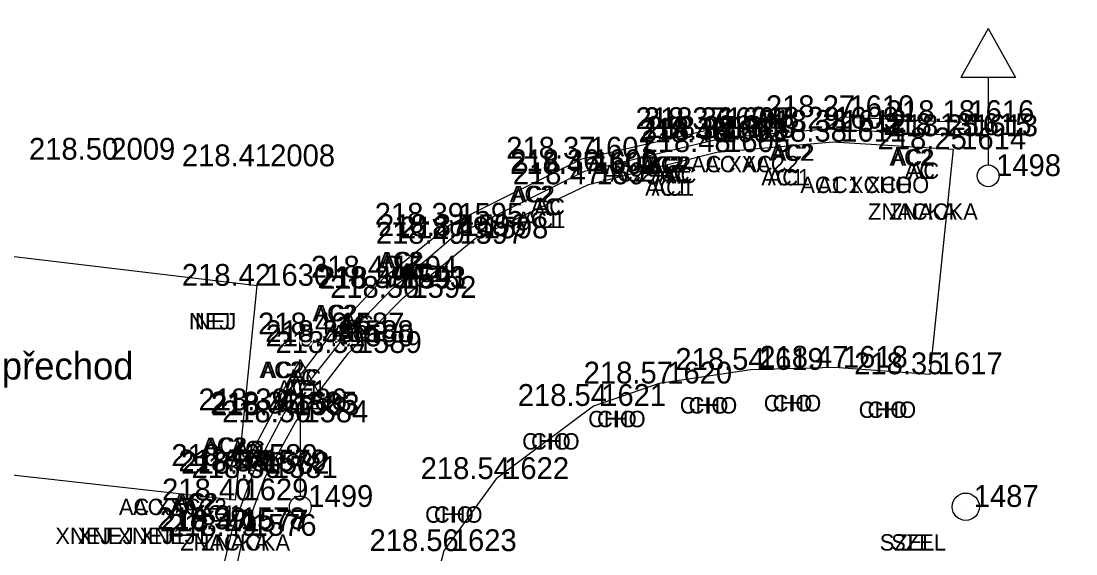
# Model space of a CAD drawing. Extents: x -471047 to -470889, y -1102859 to -1102000.
# Drawn here: x -470949.12 to -470929.78, y -1102399.08 to -1102389.32 of the extents above; entities that cross this region are included whole.
import ezdxf

# ---------------------------------------------------------------- set-up
doc = ezdxf.new("R2010")
doc.units = 0
for name, color, linetype in [('Vrstva 1', 7, 'Continuous'), ('Vrstva 19', 7, 'Continuous'), ('Vrstva 22', 7, 'Continuous'), ('Vrstva 23', 7, 'Continuous'), ('Vrstva 34', 7, 'Continuous'), ('Vrstva 35', 7, 'Continuous'), ('Vrstva 36', 7, 'Continuous'), ('Vrstva 38', 7, 'Continuous'), ('Vrstva 5', 7, 'Continuous'), ('Vrstva 7', 7, 'Continuous'), ('Vrstva 8', 7, 'Continuous'), ('Vrstva 9', 7, 'Continuous')]:
    doc.layers.add(name, color=color, linetype=linetype)

msp = doc.modelspace()

# ---------------------------------------------------------------- linework, layer by layer
at = {"layer": 'Vrstva 1'}
for points in [[(-471040.344, -1102858.385), (-471031.676, -1102846.187), (-471026.357, -1102838.629), (-471023.212, -1102833.975), (-471019.21, -1102827.465), (-471016.861, -1102823.272), (-471013.099, -1102815.912), (-471010.824, -1102810.955), (-471007.329, -1102802.292), (-471005.34, -1102796.515), (-471002.842, -1102787.838), (-471001.3, -1102780.997), (-471000.19, -1102774.713), (-470999.247, -1102768.204), (-470998.794, -1102764.784), (-470997.199, -1102751.812), (-470994.899, -1102732.807), (-470992.551, -1102713.262), (-470990.326, -1102694.887), (-470988.122, -1102676.57), (-470985.812, -1102657.305), (-470983.537, -1102638.407), (-470981.386, -1102620.622), (-470979.843, -1102608.014), (-470976.377, -1102579.253), (-470972.945, -1102550.69), (-470970.475, -1102530.206), (-470967.905, -1102508.801), (-470965.053, -1102485.131), (-470962.734, -1102465.9), (-470960.173, -1102444.812), (-470957.795, -1102425.103), (-470954.965, -1102401.839), (-470953.834, -1102392.574), (-470952.33, -1102379.985), (-470950.744, -1102366.853), (-470948.978, -1102352.106), (-470947.037, -1102335.844), (-470944.949, -1102318.462), (-470944.013, -1102310.745), (-470942.39, -1102297.267), (-470939.519, -1102273.45), (-470937.593, -1102257.43), (-470936.064, -1102244.81), (-470934.114, -1102228.634), (-470931.621, -1102207.856), (-470929.536, -1102190.857), (-470926.572, -1102166.31), (-470924.91, -1102152.663), (-470923.413, -1102140.333), (-470921.923, -1102127.669), (-470921.155, -1102120.084), (-470920.446, -1102109.574), (-470919.912, -1102099.137), (-470919.63, -1102088.981), (-470919.523, -1102081.193), (-470919.563, -1102070.395), (-470919.714, -1102064.236), (-470920.134, -1102054.704), (-470920.462, -1102047.615), (-470920.599, -1102044.52), (-470920.743, -1102041.873), (-470921.125, -1102034.455), (-470921.774, -1102030.337), (-470922.418, -1102027.787), (-470923.734, -1102023.93), (-470924.872, -1102021.434), (-470926.752, -1102018.182), (-470927.953, -1102016.45), (-470929.616, -1102014.424), (-470932.252, -1102011.756), (-470935.111, -1102009.425), (-470938.391, -1102007.371), (-470942.651, -1102005.401)], [(-471041.328, -1102857.18), (-471032.144, -1102844.242), (-471027.583, -1102837.763), (-471024.388, -1102833.028), (-471020.451, -1102826.6), (-471018.089, -1102822.378), (-471014.542, -1102815.445), (-471012.233, -1102810.418), (-471009.247, -1102803.108), (-471006.795, -1102796.098), (-471004.315, -1102787.532), (-471002.782, -1102780.723), (-471001.674, -1102774.458), (-471000.75, -1102768.095), (-471000.28, -1102764.601), (-470998.692, -1102751.741), (-470996.378, -1102732.635), (-470994.028, -1102713.058), (-470991.808, -1102694.749), (-470989.616, -1102676.447), (-470987.284, -1102657.013), (-470985.031, -1102638.272), (-470982.87, -1102620.431), (-470981.334, -1102607.933), (-470977.881, -1102579.263), (-470974.429, -1102550.492), (-470971.964, -1102530.054), (-470969.391, -1102508.607), (-470966.54, -1102484.984), (-470964.231, -1102465.853), (-470961.679, -1102444.752), (-470959.304, -1102425.078), (-470956.455, -1102401.634), (-470955.339, -1102392.489), (-470953.812, -1102379.71), (-470952.249, -1102366.808), (-470950.479, -1102352.023), (-470948.536, -1102335.868), (-470946.426, -1102318.233), (-470945.493, -1102310.531), (-470943.864, -1102297.013), (-470940.984, -1102273.071), (-470939.078, -1102257.195), (-470937.559, -1102244.684), (-470935.592, -1102228.353), (-470933.101, -1102207.653), (-470931.011, -1102190.57), (-470928.046, -1102166.021), (-470926.409, -1102152.578), (-470924.898, -1102140.121), (-470923.427, -1102127.544), (-470922.647, -1102119.826), (-470921.919, -1102109.229), (-470921.42, -1102099.134), (-470921.127, -1102089.016), (-470921.023, -1102081.453), (-470921.061, -1102070.468), (-470921.209, -1102064.314), (-470921.666, -1102053.966), (-470922.156, -1102043.345), (-470922.299, -1102039.934), (-470922.637, -1102034.36), (-470923.091, -1102031.241), (-470923.847, -1102028.247), (-470925.083, -1102024.594), (-470926.222, -1102022.086), (-470928.04, -1102018.943), (-470929.138, -1102017.357), (-470930.929, -1102015.175), (-470933.062, -1102013.049), (-470936.379, -1102010.368), (-470939.169, -1102008.662), (-470942.899, -1102006.906), (-470945.661, -1102005.908)], [(-471043.557, -1102855.955), (-471035.129, -1102844.026), (-471029.872, -1102836.499), (-471026.577, -1102831.578), (-471022.675, -1102825.415), (-471020.123, -1102821.053), (-471016.667, -1102814.59), (-471014.208, -1102809.45), (-471011.177, -1102802.451), (-471008.55, -1102795.333), (-471006.082, -1102787.209), (-471004.464, -1102780.376), (-471003.265, -1102774.167), (-471002.327, -1102767.948), (-471001.636, -1102762.527), (-471000.297, -1102751.605), (-470997.959, -1102732.524), (-470995.602, -1102712.802), (-470993.412, -1102694.623), (-470991.21, -1102676.17), (-470988.891, -1102656.857), (-470986.625, -1102638.083), (-470984.455, -1102620.195), (-470982.936, -1102607.733), (-470979.497, -1102579.223), (-470976.023, -1102550.279), (-470973.554, -1102529.822), (-470970.991, -1102508.497), (-470968.146, -1102484.787), (-470965.835, -1102465.72), (-470963.284, -1102444.529), (-470960.91, -1102424.942), (-470958.043, -1102401.343), (-470956.946, -1102392.356), (-470955.396, -1102379.408), (-470953.851, -1102366.636), (-470952.049, -1102351.733), (-470950.124, -1102335.611), (-470948.034, -1102318.083), (-470947.094, -1102310.328), (-470945.421, -1102296.51), (-470942.58, -1102272.848), (-470940.675, -1102256.948), (-470939.176, -1102244.526), (-470937.187, -1102228.174), (-470934.708, -1102207.467), (-470932.621, -1102190.433), (-470929.634, -1102165.778), (-470928.004, -1102152.415), (-470926.45, -1102139.595), (-470925.003, -1102127.418), (-470924.249, -1102119.695), (-470923.515, -1102109.093), (-470923.018, -1102099.069), (-470922.711, -1102088.911), (-470922.643, -1102081.356), (-470922.797, -1102070.414), (-470923.018, -1102064.454), (-470923.52, -1102053.203), (-470923.823, -1102047.529), (-470924.123, -1102041.506), (-470924.462, -1102037.486), (-470924.934, -1102031.904), (-470925.664, -1102028.672), (-470926.771, -1102025.506), (-470927.959, -1102022.914), (-470929.674, -1102020.028), (-470930.76, -1102018.498), (-470932.447, -1102016.478), (-470935.215, -1102013.816), (-470937.644, -1102011.98), (-470940.381, -1102010.371), (-470943.968, -1102008.669), (-470947.145, -1102007.524), (-470950.874, -1102006.74)], [(-471044.756, -1102855.056), (-471036.376, -1102843.177), (-471031.167, -1102835.741), (-471027.859, -1102830.8), (-471023.934, -1102824.593), (-471021.43, -1102820.312), (-471018.011, -1102813.91), (-471015.536, -1102808.75), (-471012.578, -1102801.897), (-471009.95, -1102794.77), (-471007.561, -1102786.914), (-471005.936, -1102780.074), (-471004.727, -1102773.818), (-471003.828, -1102767.827), (-471003.121, -1102762.345), (-471001.787, -1102751.467), (-470999.446, -1102732.348), (-470997.073, -1102712.539), (-470994.902, -1102694.521), (-470992.696, -1102676.023), (-470990.376, -1102656.68), (-470988.131, -1102638.071), (-470985.947, -1102620.018), (-470984.417, -1102607.512), (-470980.993, -1102579.08), (-470977.514, -1102550.137), (-470975.048, -1102529.649), (-470972.488, -1102508.37), (-470969.618, -1102484.508), (-470967.34, -1102465.669), (-470964.767, -1102444.39), (-470962.402, -1102424.781), (-470959.534, -1102401.193), (-470958.432, -1102392.151), (-470956.883, -1102379.208), (-470955.335, -1102366.424), (-470953.535, -1102351.506), (-470951.606, -1102335.399), (-470949.519, -1102317.94), (-470948.575, -1102310.159), (-470946.889, -1102296.144), (-470944.056, -1102272.618), (-470942.139, -1102256.659), (-470940.657, -1102244.341), (-470938.638, -1102227.749), (-470936.19, -1102207.298), (-470934.102, -1102190.255), (-470931.124, -1102165.639), (-470929.492, -1102152.254), (-470927.915, -1102139.252), (-470926.46, -1102127.103), (-470925.74, -1102119.604), (-470925.012, -1102108.913), (-470924.523, -1102099.054), (-470924.217, -1102088.866), (-470924.148, -1102081.334), (-470924.301, -1102070.391), (-470924.518, -1102064.43), (-470924.97, -1102054.435), (-470925.588, -1102041.569), (-470925.963, -1102035.313), (-470926.405, -1102032.225), (-470927.078, -1102029.198), (-470928.123, -1102026.148), (-470929.318, -1102023.558), (-470930.84, -1102020.97), (-470931.868, -1102019.515), (-470933.443, -1102017.605), (-470936.26, -1102014.885), (-470938.429, -1102013.255), (-470941.213, -1102011.639), (-470944.847, -1102009.927), (-470947.723, -1102008.912), (-470951.444, -1102008.161), (-470954.511, -1102007.931), (-470957.895, -1102008.041)]]:
    msp.add_spline(points, degree=3, dxfattribs=at)
at = {"layer": 'Vrstva 19'}
for p, q in [((-470931.386, -1102389.455), (-470931.886, -1102390.355)), ((-470931.386, -1102389.455), (-470930.886, -1102390.355)), ((-470930.886, -1102390.355), (-470931.886, -1102390.355)), ((-470931.386, -1102390.355), (-470931.386, -1102391.955)), ((-470943.999, -1102395.522), (-470944.499, -1102396.422)), ((-470943.999, -1102395.522), (-470943.499, -1102396.422)), ((-470943.499, -1102396.422), (-470944.499, -1102396.422)), ((-470943.999, -1102396.422), (-470943.999, -1102398.022))]:
    msp.add_line(p, q, dxfattribs=at)
for centre in [(-470931.386, -1102392.155), (-470943.999, -1102398.222)]:
    msp.add_circle(centre, 0.2, dxfattribs=at)
at = {"layer": 'Vrstva 23'}
msp.add_circle((-470931.799, -1102398.216), 0.25, dxfattribs=at)
at = {"layer": 'Vrstva 34'}
for p, q in [((-470934.08, -1102391.08), (-470934.08, -1102391.08)), ((-470936.47, -1102391.3), (-470936.47, -1102391.3)), ((-470936.34, -1102391.3), (-470936.34, -1102391.3)), ((-470934.36, -1102391.29), (-470934.36, -1102391.29)), ((-470931.88, -1102391.17), (-470931.88, -1102391.17)), ((-470936.44, -1102391.54), (-470936.44, -1102391.54)), ((-470936.38, -1102391.49), (-470936.38, -1102391.49)), ((-470936.27, -1102391.46), (-470936.27, -1102391.46)), ((-470934.23, -1102391.53), (-470934.23, -1102391.53)), ((-470934.22, -1102391.35), (-470934.22, -1102391.35)), ((-470931.93, -1102391.41), (-470931.93, -1102391.41)), ((-470931.81, -1102391.43), (-470931.81, -1102391.43)), ((-470936.36, -1102391.72), (-470936.36, -1102391.72)), ((-470932.03, -1102391.67), (-470932.03, -1102391.67)), ((-470947.63, -1102391.86), (-470947.63, -1102391.86)), ((-470938.84, -1102391.84), (-470938.84, -1102391.84)), ((-470944.7, -1102391.98), (-470944.7, -1102391.98)), ((-470938.79, -1102392.07), (-470938.79, -1102392.07)), ((-470938.77, -1102392.12), (-470938.77, -1102392.12)), ((-470938.72, -1102392.31), (-470938.72, -1102392.31)), ((-470931.39, -1102392.16), (-470931.39, -1102392.16)), ((-470941.25, -1102393.05), (-470941.25, -1102393.05)), ((-470941.19, -1102393.26), (-470941.19, -1102393.26)), ((-470941.23, -1102393.4), (-470941.23, -1102393.4)), ((-470940.79, -1102393.3), (-470940.79, -1102393.3)), ((-470942.46, -1102394.02), (-470942.46, -1102394.02)), ((-470944.79, -1102394.17), (-470944.79, -1102394.17)), ((-470942.3, -1102394.21), (-470942.3, -1102394.21)), ((-470942.27, -1102394.22), (-470942.27, -1102394.22)), ((-470942.11, -1102394.39), (-470942.11, -1102394.39)), ((-470943.43, -1102395.06), (-470943.43, -1102395.06)), ((-470943.26, -1102395.2), (-470943.26, -1102395.2)), ((-470943.25, -1102395.28), (-470943.25, -1102395.28)), ((-470943.11, -1102395.4), (-470943.11, -1102395.4)), ((-470935.74, -1102395.71), (-470935.74, -1102395.71)), ((-470934.2, -1102395.67), (-470934.2, -1102395.67)), ((-470932.46, -1102395.79), (-470932.46, -1102395.79)), ((-470937.42, -1102395.96), (-470937.42, -1102395.96)), ((-470938.63, -1102396.37), (-470938.63, -1102396.37)), ((-470944.48, -1102396.45), (-470944.48, -1102396.45)), ((-470944.29, -1102396.51), (-470944.29, -1102396.51)), ((-470944.25, -1102396.54), (-470944.25, -1102396.54)), ((-470944.09, -1102396.67), (-470944.09, -1102396.67)), ((-470945.02, -1102397.47), (-470945.02, -1102397.47)), ((-470944.85, -1102397.57), (-470944.85, -1102397.57)), ((-470944.8, -1102397.61), (-470944.8, -1102397.61)), ((-470944.65, -1102397.69), (-470944.65, -1102397.69)), ((-470940.41, -1102397.71), (-470940.41, -1102397.71)), ((-470945.19, -1102398.1), (-470945.19, -1102398.1)), ((-470944, -1102398.22), (-470944, -1102398.22)), ((-470931.8, -1102398.22), (-470931.8, -1102398.22)), ((-470945.24, -1102398.63), (-470945.24, -1102398.63)), ((-470945.19, -1102398.67), (-470945.19, -1102398.67)), ((-470945.04, -1102398.75), (-470945.04, -1102398.75)), ((-470941.37, -1102399.03), (-470941.37, -1102399.03))]:
    msp.add_line(p, q, dxfattribs=at)
at = {"layer": 'Vrstva 5'}
for p, q in [((-470934.361, -1102391.295), (-470934.079, -1102391.077)), ((-470934.079, -1102391.077), (-470931.877, -1102391.169)), ((-470938.837, -1102391.841), (-470936.466, -1102391.302)), ((-470936.466, -1102391.302), (-470936.341, -1102391.301)), ((-470936.341, -1102391.301), (-470936.273, -1102391.456)), ((-470941.249, -1102393.046), (-470938.837, -1102391.841)), ((-470942.463, -1102394.02), (-470941.249, -1102393.046)), ((-470943.432, -1102395.063), (-470942.463, -1102394.02)), ((-470944.48, -1102396.449), (-470943.432, -1102395.063)), ((-470945.023, -1102397.472), (-470944.48, -1102396.449)), ((-470944.852, -1102397.574), (-470945.023, -1102397.472))]:
    msp.add_line(p, q, dxfattribs=at)
at = {"layer": 'Vrstva 7'}
for p, q in [((-470936.361, -1102391.724), (-470934.235, -1102391.53)), ((-470934.235, -1102391.53), (-470932.026, -1102391.669)), ((-470938.716, -1102392.311), (-470936.361, -1102391.724)), ((-470940.791, -1102393.304), (-470938.716, -1102392.311)), ((-470942.113, -1102394.387), (-470940.791, -1102393.304)), ((-470943.113, -1102395.401), (-470942.113, -1102394.387)), ((-470944.086, -1102396.669), (-470943.113, -1102395.401)), ((-470944.652, -1102397.687), (-470944.086, -1102396.669)), ((-470945.038, -1102398.748), (-470944.652, -1102397.687)), ((-470945.474, -1102400.707), (-470945.038, -1102398.748))]:
    msp.add_line(p, q, dxfattribs=at)
at = {"layer": 'Vrstva 8'}
for p, q in [((-470936.273, -1102391.456), (-470934.361, -1102391.295)), ((-470934.361, -1102391.295), (-470931.928, -1102391.413)), ((-470938.791, -1102392.07), (-470936.381, -1102391.488)), ((-470936.381, -1102391.488), (-470936.273, -1102391.456)), ((-470932.026, -1102391.669), (-470932.459, -1102395.794)), ((-470941.189, -1102393.264), (-470938.791, -1102392.07)), ((-470942.304, -1102394.21), (-470941.189, -1102393.264)), ((-470943.264, -1102395.2), (-470942.304, -1102394.21)), ((-470944.295, -1102396.511), (-470943.264, -1102395.2)), ((-470935.737, -1102395.711), (-470937.417, -1102395.962)), ((-470934.203, -1102395.666), (-470935.737, -1102395.711)), ((-470932.459, -1102395.794), (-470934.203, -1102395.666)), ((-470937.417, -1102395.962), (-470938.626, -1102396.373)), ((-470938.626, -1102396.373), (-470940.408, -1102397.705)), ((-470944.852, -1102397.574), (-470944.295, -1102396.511)), ((-470945.241, -1102398.626), (-470944.852, -1102397.574)), ((-470940.408, -1102397.705), (-470941.368, -1102399.026)), ((-470945.724, -1102400.649), (-470945.241, -1102398.626)), ((-470941.368, -1102399.026), (-470942.101, -1102401.878))]:
    msp.add_line(p, q, dxfattribs=at)
at = {"layer": 'Vrstva 9'}
for p, q in [((-470944.791, -1102394.172), (-470950.548, -1102393.482)), ((-470945.189, -1102398.097), (-470944.791, -1102394.172)), ((-470945.189, -1102398.097), (-470951.095, -1102397.436))]:
    msp.add_line(p, q, dxfattribs=at)

# ---------------------------------------------------------------- texts
at = {"layer": 'Vrstva 22'}
msp.add_text('přechod', height=0.5, dxfattribs=at).set_placement((-470949.472, -1102395.886))
at = {"layer": 'Vrstva 35'}
for s, p in [('AC2', (-470935.396, -1102391.88)), ('AC2', (-470935.355, -1102391.88)), ('AC2', (-470933.196, -1102391.97)), ('AC2', (-470933.155, -1102391.97)), ('AC2', (-470937.786, -1102392.1)), ('AC2', (-470937.745, -1102392.1)), ('AC2', (-470937.656, -1102392.1)), ('AC2', (-470937.615, -1102392.1)), ('AC XAC2', (-470936.835, -1102392.09)), ('AC XAC2', (-470936.576, -1102392.09)), ('AC', (-470932.919, -1102392.21)), ('AC', (-470932.844, -1102392.21)), ('AC2 AC', (-470938.459, -1102392.26)), ('AC2 AC', (-470938.309, -1102392.26)), ('AC', (-470937.369, -1102392.29)), ('AC', (-470937.294, -1102392.29)), ('AC1', (-470935.547, -1102392.33)), ('AC1', (-470935.43, -1102392.33)), ('AC1', (-470937.677, -1102392.52)), ('AC1', (-470937.56, -1102392.52)), ('AC1 XCHO', (-470934.831, -1102392.47)), ('AC1 XCHO', (-470934.519, -1102392.47)), ('AC2', (-470940.156, -1102392.64)), ('AC2', (-470940.115, -1102392.64)), ('AC', (-470939.779, -1102392.87)), ('AC', (-470939.704, -1102392.87)), ('ZNACKA', (-470933.59, -1102392.96)), ('ZNACKA', (-470933.204, -1102392.96)), ('AC1', (-470940.037, -1102393.11)), ('AC1', (-470939.92, -1102393.11)), ('AC2', (-470942.566, -1102393.85)), ('AC2', (-470942.525, -1102393.85)), ('AC', (-470942.179, -1102394.06)), ('AC1', (-470942.107, -1102394.1)), ('AC', (-470942.104, -1102394.06)), ('AC1', (-470941.99, -1102394.1)), ('AC2', (-470943.776, -1102394.82)), ('AC2', (-470943.735, -1102394.82)), ('NEJ', (-470946.04, -1102394.97)), ('NEJ', (-470945.929, -1102394.97)), ('AC', (-470943.289, -1102395.01)), ('AC', (-470943.214, -1102395.01)), ('AC1', (-470943.427, -1102395.19)), ('AC1', (-470943.31, -1102395.19)), ('AC2', (-470944.746, -1102395.86)), ('AC2', (-470944.705, -1102395.86)), ('AC', (-470944.249, -1102396)), ('AC', (-470944.174, -1102396)), ('AC1', (-470944.427, -1102396.2)), ('AC1', (-470944.31, -1102396.2)), ('CHO', (-470935.501, -1102396.47)), ('CHO', (-470935.339, -1102396.47)), ('CHO', (-470937.041, -1102396.51)), ('CHO', (-470936.879, -1102396.51)), ('CHO', (-470933.761, -1102396.59)), ('CHO', (-470933.599, -1102396.59)), ('CHO', (-470938.721, -1102396.76)), ('CHO', (-470938.559, -1102396.76)), ('AC2', (-470945.796, -1102397.25)), ('AC2', (-470945.755, -1102397.25)), ('CHO', (-470939.931, -1102397.17)), ('CHO', (-470939.769, -1102397.17)), ('AC', (-470945.279, -1102397.31)), ('AC', (-470945.204, -1102397.31)), ('AC1', (-470945.407, -1102397.47)), ('AC1', (-470945.29, -1102397.47)), ('AC XAC2', (-470947.325, -1102398.37)), ('AC XAC2', (-470947.066, -1102398.37)), ('AC2', (-470946.336, -1102398.27)), ('AC2', (-470946.295, -1102398.27)), ('AC1', (-470945.967, -1102398.49)), ('AC1', (-470945.85, -1102398.49)), ('CHO', (-470941.711, -1102398.51)), ('CHO', (-470941.549, -1102398.51)), ('XNEJ XNEJ1', (-470948.49, -1102398.9)), ('XNEJ XNEJ1', (-470948.082, -1102398.9)), ('ZNACKA', (-470946.2, -1102399.02)), ('ZNACKA', (-470945.814, -1102399.02)), ('SZEL', (-470933.375, -1102399.02)), ('SZEL', (-470933.164, -1102399.02))]:
    msp.add_text(s, height=0.3, dxfattribs=at).set_placement(p)
at = {"layer": 'Vrstva 36'}
for s, p in [(' 1610', (-470934.08, -1102391.08)), (' 1616', (-470931.88, -1102391.17)), (' 1604', (-470936.47, -1102391.3)), (' 1607', (-470936.34, -1102391.3)), (' 1609', (-470934.36, -1102391.29)), (' 1612', (-470934.22, -1102391.35)), (' 1603', (-470936.44, -1102391.54)), (' 1605', (-470936.38, -1102391.49)), (' 1608', (-470936.27, -1102391.46)), (' 1611', (-470934.23, -1102391.53)), (' 1615', (-470931.93, -1102391.41)), (' 1613', (-470931.81, -1102391.43)), (' 1606', (-470936.36, -1102391.72)), (' 1614', (-470932.03, -1102391.67)), (' 2009', (-470947.63, -1102391.86)), (' 1601', (-470938.84, -1102391.84)), (' 2008', (-470944.7, -1102391.98)), (' 1600', (-470938.79, -1102392.07)), (' 1602', (-470938.77, -1102392.12)), (' 1599', (-470938.72, -1102392.31)), (' 1498', (-470931.39, -1102392.16)), (' 1595', (-470941.25, -1102393.05)), (' 1596', (-470941.19, -1102393.26)), (' 1598', (-470940.79, -1102393.3)), (' 1597', (-470941.23, -1102393.4)), (' 1594', (-470942.46, -1102394.02)), (' 1630', (-470944.79, -1102394.17)), (' 1593', (-470942.3, -1102394.21)), (' 1591', (-470942.27, -1102394.22)), (' 1592', (-470942.11, -1102394.39)), (' 1587', (-470943.43, -1102395.06)), (' 1588', (-470943.26, -1102395.2)), (' 1590', (-470943.25, -1102395.28)), (' 1589', (-470943.11, -1102395.4)), (' 1619', (-470935.74, -1102395.71)), (' 1618', (-470934.2, -1102395.67)), (' 1617', (-470932.46, -1102395.79)), (' 1620', (-470937.42, -1102395.96)), (' 1621', (-470938.63, -1102396.37)), (' 1586', (-470944.48, -1102396.45)), (' 1585', (-470944.29, -1102396.51)), (' 1583', (-470944.25, -1102396.54)), (' 1584', (-470944.09, -1102396.67)), (' 1580', (-470945.02, -1102397.47)), (' 1579', (-470944.85, -1102397.57)), (' 1582', (-470944.8, -1102397.61)), (' 1581', (-470944.65, -1102397.69)), (' 1622', (-470940.41, -1102397.71)), (' 1629', (-470945.19, -1102398.1)), (' 1499', (-470944, -1102398.22)), (' 1487', (-470931.8, -1102398.22)), (' 1578', (-470945.24, -1102398.63)), (' 1577', (-470945.19, -1102398.67)), (' 1576', (-470945.04, -1102398.75)), (' 1623', (-470941.37, -1102399.03))]:
    msp.add_text(s, height=0.4, dxfattribs=at).set_placement(p)
at = {"layer": 'Vrstva 38'}
for s, p in [('218.27 ', (-470935.463, -1102391.08)), ('218.18 ', (-470933.264, -1102391.17)), ('218.37 ', (-470937.853, -1102391.3)), ('218.36 ', (-470937.7, -1102391.3)), ('218.29 ', (-470935.744, -1102391.29)), ('218.38 ', (-470935.604, -1102391.35)), ('218.46 ', (-470937.8, -1102391.54)), ('218.35 ', (-470937.764, -1102391.49)), ('218.35 ', (-470937.654, -1102391.46)), ('218.38 ', (-470935.614, -1102391.53)), ('218.13 ', (-470933.313, -1102391.41)), ('218.25 ', (-470933.194, -1102391.43)), ('218.48 ', (-470937.744, -1102391.72)), ('218.25 ', (-470933.414, -1102391.67)), ('218.50 ', (-470948.973, -1102391.86)), ('218.37 ', (-470940.223, -1102391.84)), ('218.41 ', (-470946.17, -1102391.98)), ('218.47 ', (-470940.153, -1102392.12)), ('218.36 ', (-470940.15, -1102392.07)), ('218.47 ', (-470940.103, -1102392.31)), ('218.39 ', (-470942.634, -1102393.05)), ('218.37 ', (-470942.573, -1102393.26)), ('218.49 ', (-470942.174, -1102393.3)), ('218.49 ', (-470942.614, -1102393.4)), ('218.40 ', (-470943.803, -1102394.02)), ('218.42 ', (-470946.171, -1102394.17)), ('218.39 ', (-470943.684, -1102394.21)), ('218.48 ', (-470943.654, -1102394.22)), ('218.50 ', (-470943.453, -1102394.39)), ('218.40 ', (-470944.773, -1102395.06)), ('218.38 ', (-470944.644, -1102395.2)), ('218.49 ', (-470944.634, -1102395.28)), ('218.50 ', (-470944.453, -1102395.4)), ('218.54 ', (-470937.122, -1102395.71)), ('218.47 ', (-470935.583, -1102395.67)), ('218.35 ', (-470933.844, -1102395.79)), ('218.57 ', (-470938.803, -1102395.96)), ('218.54 ', (-470940.012, -1102396.37)), ('218.39 ', (-470945.864, -1102396.45)), ('218.36 ', (-470945.65, -1102396.51)), ('218.47 ', (-470945.633, -1102396.54)), ('218.50 ', (-470945.433, -1102396.67)), ('218.40 ', (-470946.363, -1102397.47)), ('218.38 ', (-470946.234, -1102397.57)), ('218.47 ', (-470946.183, -1102397.61)), ('218.50 ', (-470945.993, -1102397.69)), ('218.54 ', (-470941.792, -1102397.71)), ('218.40 ', (-470946.533, -1102398.1)), ('218.39 ', (-470946.624, -1102398.63)), ('218.47 ', (-470946.573, -1102398.67)), ('218.49 ', (-470946.424, -1102398.75)), ('218.56 ', (-470942.73, -1102399.03))]:
    msp.add_text(s, height=0.4, dxfattribs=at).set_placement(p)

doc.saveas('drawing.dxf')
